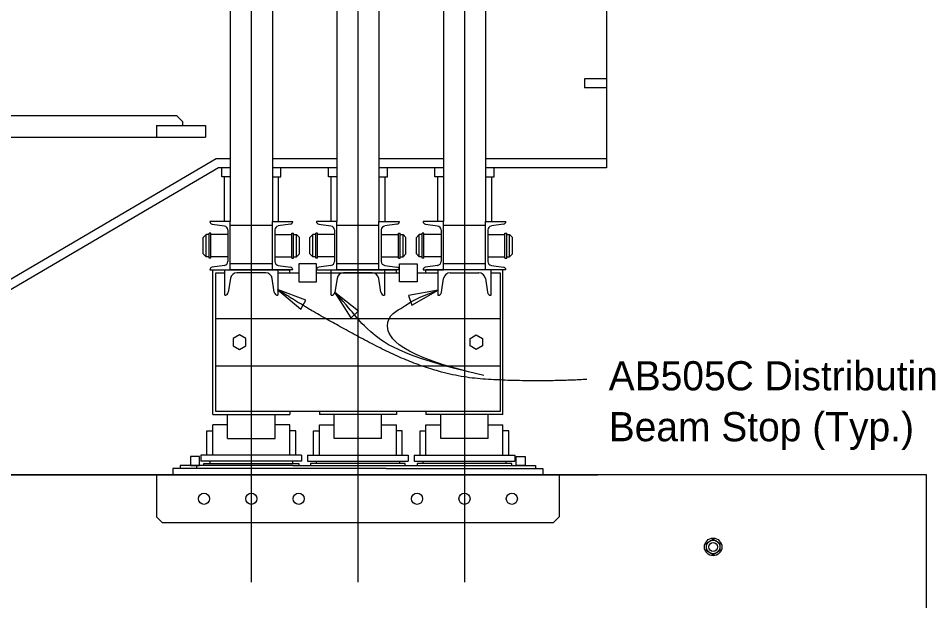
# Model space of a CAD drawing. Extents: x -4.4 to 30.2, y 1.2 to 17.8.
# Drawn here: x 22.971 to 27.789, y 8.08 to 11.153 of the extents above; entities that cross this region are included whole.
import ezdxf

# ---------------------------------------------------------------- set-up
doc = ezdxf.new("R2010")
doc.units = 0
for name, color, linetype in [('CL_Minor', 7, 'Continuous'), ('Dimension', 7, 'Continuous'), ('Miscellaneous', 7, 'Continuous'), ('SteelMisc', 7, 'Continuous'), ('Wood', 7, 'Continuous')]:
    doc.layers.add(name, color=color, linetype=linetype)

msp = doc.modelspace()

# ---------------------------------------------------------------- linework, layer by layer
at = {"layer": 'CL_Minor'}
for p, q in [((25.3273, 17.6955), (25.3273, 8.1779)), ((24.2019, 16.9098), (24.2019, 8.1779)), ((24.7646, 16.9098), (24.7646, 8.1779))]:
    msp.add_line(p, q, dxfattribs=at)
at = {"layer": 'Dimension'}
for points in [[(24.3408, 9.7224), (24.4626, 9.6193), (24.4892, 9.6658)], [(24.7293, 9.573), (24.643, 9.7082), (24.7683, 9.6095)], [(25.188, 9.7195), (25.0321, 9.6905), (25.0502, 9.6399)]]:
    msp.add_lwpolyline(points, close=True, dxfattribs=at)
for points, degree in [([(25.974, 9.2475), (25.6657, 9.2315), (25.152, 9.2707), (24.5315, 9.5973), (24.3408, 9.7224)], 2), ([(25.429, 9.2693), (24.98, 9.3691), (24.7927, 9.5306), (24.7496, 9.5842), (24.7132, 9.6307), (24.643, 9.7082)], 3), ([(25.429, 9.2693), (24.98, 9.3691), (24.8654, 9.5681), (25.0288, 9.6326), (25.0332, 9.6602), (25.188, 9.7195)], 3)]:
    msp.add_open_spline(points, degree=degree, dxfattribs=at)
at = {"layer": 'Miscellaneous'}
for points in [[(23.9831, 8.8167), (23.9831, 8.8048), (24.4208, 8.8048), (24.4208, 8.8167)], [(24.9834, 8.8167), (24.9834, 8.8048), (24.5457, 8.8048), (24.5457, 8.8167)], [(25.5461, 8.8167), (25.5461, 8.8048), (25.1084, 8.8048), (25.1084, 8.8167)], [(23.9517, 8.8048), (24.4521, 8.8048), (24.4521, 8.7929)], [(23.9517, 8.7929), (23.9517, 8.8048)], [(25.0148, 8.8048), (24.5144, 8.8048), (24.5144, 8.7929)], [(25.0148, 8.7929), (25.0148, 8.8048)], [(25.5775, 8.8048), (25.0771, 8.8048), (25.0771, 8.7929)], [(25.5775, 8.7929), (25.5775, 8.8048)]]:
    msp.add_lwpolyline(points, dxfattribs=at)
at = {"layer": 'SteelMisc'}
for p, q in [((24.0906, 13.4491), (24.0906, 10.0806)), ((25.2161, 13.4491), (25.2161, 10.0806)), ((25.4385, 13.4491), (25.4385, 10.0806)), ((24.3131, 13.3329), (24.3131, 10.0806)), ((24.6534, 12.6443), (24.6534, 10.0806)), ((24.8758, 12.3396), (24.8758, 10.0806)), ((26.0776, 11.2551), (26.0776, 10.3648)), ((26.0776, 10.8338), (25.9607, 10.8338)), ((25.9607, 10.8338), (25.9607, 10.7861)), ((26.0776, 10.7861), (25.9607, 10.7861)), ((19.4067, 10.6401), (23.8077, 10.6401)), ((23.8077, 10.6401), (23.839, 10.6081)), ((23.839, 10.6081), (23.839, 10.5874)), ((23.7007, 10.5874), (23.9602, 10.5874)), ((23.7007, 10.5874), (23.7007, 10.5256)), ((23.9602, 10.5874), (23.9602, 10.5256)), ((19.1446, 10.5256), (23.9602, 10.5256)), ((24.0156, 10.4125), (22.5807, 9.5699)), ((24.0906, 10.4125), (24.0156, 10.4125)), ((24.6534, 10.4125), (24.3131, 10.4125)), ((25.2161, 10.4125), (24.8758, 10.4125)), ((26.0776, 10.4125), (25.4385, 10.4125)), ((24.0281, 10.3648), (22.5933, 9.5222)), ((24.0906, 10.3648), (24.0281, 10.3648)), ((24.0459, 10.3171), (24.0459, 10.3648)), ((24.6534, 10.3648), (24.3131, 10.3648)), ((24.3578, 10.3171), (24.3578, 10.3648)), ((24.6086, 10.3171), (24.6086, 10.3648)), ((25.2161, 10.3648), (24.8758, 10.3648)), ((24.9205, 10.3171), (24.9205, 10.3648)), ((25.1713, 10.3171), (25.1713, 10.3648)), ((26.0776, 10.3648), (25.4385, 10.3648)), ((25.4832, 10.3171), (25.4832, 10.3648)), ((24.0906, 10.3171), (24.0459, 10.3171)), ((24.0593, 10.3171), (24.0593, 10.0806)), ((24.3131, 10.3171), (24.3578, 10.3171)), ((24.3444, 10.3171), (24.3444, 10.0806)), ((24.6534, 10.3171), (24.6086, 10.3171)), ((24.6221, 10.3171), (24.6221, 10.0806)), ((24.8758, 10.3171), (24.9205, 10.3171)), ((24.9071, 10.3171), (24.9071, 10.0806)), ((25.2161, 10.3171), (25.1713, 10.3171)), ((25.1848, 10.3171), (25.1848, 10.0806)), ((25.4385, 10.3171), (25.4832, 10.3171)), ((25.4698, 10.3171), (25.4698, 10.0806)), ((24.0906, 10.0806), (23.983, 10.0806)), ((24.0906, 9.8263), (24.0906, 10.0806)), ((24.3131, 10.0806), (24.4207, 10.0806)), ((24.3131, 9.8263), (24.3131, 10.0806)), ((24.6534, 10.0806), (24.5457, 10.0806)), ((24.6534, 9.8263), (24.6534, 10.0806)), ((24.8758, 10.0806), (24.9834, 10.0806)), ((24.8758, 9.8263), (24.8758, 10.0806)), ((25.2161, 10.0806), (25.1085, 10.0806)), ((25.2161, 9.8263), (25.2161, 10.0806)), ((25.4385, 10.0806), (25.5461, 10.0806)), ((25.4385, 9.8263), (25.4385, 10.0806)), ((23.9954, 10.0669), (24.0597, 10.0573)), ((24.0781, 10.0369), (24.0781, 9.87)), ((24.0906, 10.0623), (24.3131, 10.0623)), ((24.3256, 10.0369), (24.3256, 9.87)), ((24.4083, 10.0669), (24.344, 10.0573)), ((24.5582, 10.0669), (24.6225, 10.0573)), ((24.6409, 10.0369), (24.6409, 9.87)), ((24.6534, 10.0623), (24.8758, 10.0623)), ((24.8883, 10.0369), (24.8883, 9.87)), ((24.971, 10.0669), (24.9067, 10.0573)), ((25.1209, 10.0669), (25.1852, 10.0573)), ((25.2036, 10.0369), (25.2036, 9.87)), ((25.2161, 10.0623), (25.4385, 10.0623)), ((25.451, 10.0369), (25.451, 9.87)), ((25.5337, 10.0669), (25.4694, 10.0573)), ((23.9635, 10.0122), (23.9479, 9.9963)), ((23.9479, 9.9106), (23.9479, 9.9963)), ((23.9635, 9.8947), (23.9635, 10.0122)), ((23.9791, 10.0122), (23.9635, 10.0122)), ((23.9791, 9.8871), (23.9791, 10.0198)), ((23.9879, 10.0198), (23.9791, 10.0198)), ((23.9879, 9.8871), (23.9879, 10.0198)), ((24.0781, 10.0122), (23.9879, 10.0122)), ((24.3256, 10.0122), (24.4158, 10.0122)), ((24.4158, 10.0198), (24.4246, 10.0198)), ((24.4158, 9.8871), (24.4158, 10.0198)), ((24.4246, 9.8871), (24.4246, 10.0198)), ((24.4246, 10.0122), (24.4402, 10.0122)), ((24.4402, 9.8947), (24.4402, 10.0122)), ((24.4402, 10.0122), (24.4558, 9.9963)), ((24.4558, 9.9106), (24.4558, 9.9963)), ((24.5262, 10.0122), (24.5106, 9.9963)), ((24.5106, 9.9106), (24.5106, 9.9963)), ((24.5262, 9.8947), (24.5262, 10.0122)), ((24.5418, 10.0122), (24.5262, 10.0122)), ((24.5418, 9.8871), (24.5418, 10.0198)), ((24.5506, 10.0198), (24.5418, 10.0198)), ((24.5506, 9.8871), (24.5506, 10.0198)), ((24.6409, 10.0122), (24.5506, 10.0122)), ((24.8883, 10.0122), (24.9785, 10.0122)), ((24.9785, 10.0198), (24.9873, 10.0198)), ((24.9785, 9.8871), (24.9785, 10.0198)), ((24.9873, 9.8871), (24.9873, 10.0198)), ((24.9873, 10.0122), (25.0029, 10.0122)), ((25.0029, 9.8947), (25.0029, 10.0122)), ((25.0029, 10.0122), (25.0185, 9.9963)), ((25.0185, 9.9106), (25.0185, 9.9963)), ((25.0889, 10.0122), (25.0733, 9.9963)), ((25.0733, 9.9106), (25.0733, 9.9963)), ((25.0889, 9.8947), (25.0889, 10.0122)), ((25.1045, 10.0122), (25.0889, 10.0122)), ((25.1045, 9.8871), (25.1045, 10.0198)), ((25.1133, 10.0198), (25.1045, 10.0198)), ((25.1133, 9.8871), (25.1133, 10.0198)), ((25.2036, 10.0122), (25.1133, 10.0122)), ((25.451, 10.0122), (25.5412, 10.0122)), ((25.5412, 10.0198), (25.5501, 10.0198)), ((25.5412, 9.8871), (25.5412, 10.0198)), ((25.5501, 9.8871), (25.5501, 10.0198)), ((25.5501, 10.0122), (25.5657, 10.0122)), ((25.5657, 9.8947), (25.5657, 10.0122)), ((25.5657, 10.0122), (25.5813, 9.9963)), ((25.5813, 9.9106), (25.5813, 9.9963)), ((23.9635, 9.8947), (23.9479, 9.9106)), ((23.9791, 9.8947), (23.9635, 9.8947)), ((23.9879, 9.8871), (23.9791, 9.8871)), ((24.0781, 9.8947), (23.9879, 9.8947)), ((24.3256, 9.8947), (24.4158, 9.8947)), ((24.4158, 9.8871), (24.4246, 9.8871)), ((24.4246, 9.8947), (24.4402, 9.8947)), ((24.4402, 9.8947), (24.4558, 9.9106)), ((24.5262, 9.8947), (24.5106, 9.9106)), ((24.5418, 9.8947), (24.5262, 9.8947)), ((24.5506, 9.8871), (24.5418, 9.8871)), ((24.6409, 9.8947), (24.5506, 9.8947)), ((24.8883, 9.8947), (24.9785, 9.8947)), ((24.9785, 9.8871), (24.9873, 9.8871)), ((24.9873, 9.8947), (25.0029, 9.8947)), ((25.0029, 9.8947), (25.0185, 9.9106)), ((25.0889, 9.8947), (25.0733, 9.9106)), ((25.1045, 9.8947), (25.0889, 9.8947)), ((25.1133, 9.8871), (25.1045, 9.8871)), ((25.2036, 9.8947), (25.1133, 9.8947)), ((25.451, 9.8947), (25.5412, 9.8947)), ((25.5412, 9.8871), (25.5501, 9.8871)), ((25.5501, 9.8947), (25.5657, 9.8947)), ((25.5657, 9.8947), (25.5813, 9.9106)), ((24.0597, 9.8496), (23.9954, 9.84)), ((24.3131, 9.8581), (24.0906, 9.8581)), ((24.344, 9.8496), (24.4083, 9.84)), ((24.6225, 9.8496), (24.5582, 9.84)), ((24.8758, 9.8581), (24.6534, 9.8581)), ((24.9067, 9.8496), (24.971, 9.84)), ((25.1852, 9.8496), (25.1209, 9.84)), ((25.4385, 9.8581), (25.2161, 9.8581)), ((25.4694, 9.8496), (25.5337, 9.84)), ((23.983, 9.8263), (24.0906, 9.8263)), ((23.9987, 9.0631), (23.9987, 9.8263)), ((23.9987, 9.8263), (24.4051, 9.8263)), ((24.0612, 9.6918), (24.0612, 9.8263)), ((24.0612, 9.8263), (24.3425, 9.8263)), ((24.0917, 9.7808), (24.0803, 9.7082)), ((24.3131, 9.8263), (24.0906, 9.8263)), ((24.2781, 9.81), (24.1257, 9.81)), ((24.3234, 9.7082), (24.312, 9.7808)), ((24.4207, 9.8263), (24.3131, 9.8263)), ((24.3425, 9.8263), (24.3425, 9.6918)), ((24.4051, 9.8104), (24.4051, 9.8263)), ((24.5457, 9.8263), (24.6534, 9.8263)), ((24.5614, 9.8263), (24.9679, 9.8263)), ((24.6239, 9.6918), (24.6239, 9.8263)), ((24.6239, 9.8263), (24.9053, 9.8263)), ((24.6544, 9.7808), (24.643, 9.7082)), ((24.8758, 9.8263), (24.6534, 9.8263)), ((24.8408, 9.81), (24.6884, 9.81)), ((24.8861, 9.7082), (24.8747, 9.7808)), ((24.9834, 9.8263), (24.8758, 9.8263)), ((24.9053, 9.8263), (24.9053, 9.6918)), ((24.9679, 9.8104), (24.9679, 9.8263)), ((25.1085, 9.8263), (25.2161, 9.8263)), ((25.1241, 9.8104), (25.1241, 9.8263)), ((25.5305, 9.8263), (25.1241, 9.8263)), ((25.1868, 9.8263), (25.1868, 9.6918)), ((25.4682, 9.8263), (25.1868, 9.8263)), ((25.206, 9.7082), (25.2173, 9.7808)), ((25.4385, 9.8263), (25.2161, 9.8263)), ((25.2513, 9.81), (25.4037, 9.81)), ((25.4377, 9.7808), (25.449, 9.7082)), ((25.5461, 9.8263), (25.4385, 9.8263)), ((25.4682, 9.6918), (25.4682, 9.8263)), ((25.5305, 9.0631), (25.5305, 9.8263)), ((24.0143, 9.5694), (25.5149, 9.5694)), ((24.0143, 9.32), (25.5149, 9.32)), ((23.9987, 9.0631), (24.4051, 9.0631)), ((24.0768, 8.9359), (24.0768, 9.0631)), ((24.327, 8.9359), (24.327, 9.0631)), ((24.4051, 9.079), (24.4051, 9.0631)), ((24.5614, 9.079), (24.5614, 9.0631)), ((24.9678, 9.0631), (24.5614, 9.0631)), ((24.6395, 8.9359), (24.6395, 9.0631)), ((24.8897, 8.9359), (24.8897, 9.0631)), ((24.9678, 9.079), (24.9678, 9.0631)), ((25.1241, 9.079), (25.1241, 9.0631)), ((25.5305, 9.0631), (25.1241, 9.0631)), ((25.2022, 8.9359), (25.2022, 9.0631)), ((25.4524, 8.9359), (25.4524, 9.0631)), ((23.9674, 8.8485), (23.9674, 8.9757)), ((23.9674, 8.9757), (23.9987, 8.9757)), ((23.9987, 8.8485), (23.9987, 9.0075)), ((24.0768, 9.0075), (23.9987, 9.0075)), ((24.4051, 9.0075), (24.327, 9.0075)), ((24.4051, 8.8485), (24.4051, 9.0075)), ((24.4364, 8.9757), (24.4051, 8.9757)), ((24.4364, 8.8485), (24.4364, 8.9757)), ((24.5301, 8.8485), (24.5301, 8.9757)), ((24.5301, 8.9757), (24.5614, 8.9757)), ((24.5614, 8.8485), (24.5614, 9.0075)), ((24.5614, 9.0075), (24.6395, 9.0075)), ((24.8897, 9.0075), (24.9678, 9.0075)), ((24.9678, 8.8485), (24.9678, 9.0075)), ((24.9991, 8.9757), (24.9678, 8.9757)), ((24.9991, 8.8485), (24.9991, 8.9757)), ((25.0928, 8.8485), (25.0928, 8.9757)), ((25.0928, 8.9757), (25.1241, 8.9757)), ((25.1241, 8.8485), (25.1241, 9.0075)), ((25.1241, 9.0075), (25.2022, 9.0075)), ((25.4524, 9.0075), (25.5305, 9.0075)), ((25.5305, 8.8485), (25.5305, 9.0075)), ((25.5618, 8.9757), (25.5305, 8.9757)), ((25.5618, 8.8485), (25.5618, 8.9757)), ((24.0768, 8.9359), (24.327, 8.9359)), ((24.8897, 8.9359), (24.6395, 8.9359)), ((25.4524, 8.9359), (25.2022, 8.9359)), ((24.4677, 8.8485), (23.9361, 8.8485)), ((23.9361, 8.8485), (23.9361, 8.8167)), ((24.4676, 8.8167), (23.9361, 8.8167)), ((24.4677, 8.8485), (24.4677, 8.8167)), ((24.4989, 8.8485), (24.4988, 8.8167)), ((24.4989, 8.8485), (25.0304, 8.8485)), ((24.4989, 8.8167), (25.0304, 8.8167)), ((25.0304, 8.8485), (25.0304, 8.8167)), ((25.0616, 8.8485), (25.0615, 8.8167)), ((25.0616, 8.8485), (25.5931, 8.8485)), ((25.0616, 8.8167), (25.5931, 8.8167)), ((25.5931, 8.8485), (25.5931, 8.8167)), ((23.7877, 8.777), (23.7877, 8.7452)), ((24.9132, 8.777), (23.7877, 8.777)), ((23.9132, 8.7929), (23.9132, 8.777)), ((24.9132, 8.777), (25.7415, 8.777)), ((25.7415, 8.777), (25.7415, 8.7452)), ((3.2586, 8.7452), (26.0322, 8.7452)), ((23.7016, 8.7452), (23.7016, 8.5227)), ((25.8275, 8.7452), (25.8275, 8.5227)), ((23.7329, 8.4909), (23.7016, 8.5227)), ((25.7962, 8.4909), (23.7329, 8.4909)), ((25.8275, 8.5227), (25.7962, 8.4909))]:
    msp.add_line(p, q, dxfattribs=at)
for points in [[(24.452, 9.7627), (24.5458, 9.7627), (24.5458, 9.8581), (24.452, 9.8581)], [(25.0773, 9.7627), (24.9835, 9.7627), (24.9835, 9.8581), (25.0773, 9.8581)], [(24.1726, 9.4252), (24.1726, 9.4642), (24.1394, 9.4837), (24.1061, 9.4642), (24.1061, 9.4252), (24.1394, 9.4057)], [(25.3566, 9.4252), (25.3566, 9.4642), (25.3898, 9.4837), (25.4231, 9.4642), (25.4231, 9.4252), (25.3898, 9.4057)], [(23.8814, 8.7929), (23.9283, 8.7929), (23.9283, 8.8406), (23.8814, 8.8406)], [(25.6478, 8.7929), (25.6009, 8.7929), (25.6009, 8.8406), (25.6478, 8.8406)], [(26.6759, 8.3845), (26.6759, 8.3428), (26.6403, 8.3219), (26.6048, 8.3428), (26.6048, 8.3845), (26.6403, 8.4054)]]:
    msp.add_lwpolyline(points, close=True, dxfattribs=at)
for points in [[(25.4682, 9.8104), (25.5149, 9.8104), (25.5149, 9.079), (24.0143, 9.079), (24.0143, 9.8104), (24.0612, 9.8104)], [(24.3425, 9.8104), (24.452, 9.8104)], [(24.5458, 9.8104), (24.9835, 9.8104)], [(25.0773, 9.8104), (25.1868, 9.8104)], [(24.4217, 8.7929), (23.8267, 8.7929), (23.8267, 8.777)], [(24.4217, 8.7929), (25.7025, 8.7929), (25.7025, 8.777)]]:
    msp.add_lwpolyline(points, dxfattribs=at)
for centre, major_axis, ratio, start_param, end_param in [((23.9979, 10.0806), (-0.0149, 0), 0.936129, 6.283185, 7.688175), ((24.4058, 10.0806), (0.0149, 0), 0.936129, 4.878195, 6.283185), ((24.5606, 10.0806), (-0.0149, 0), 0.936129, 6.283185, 7.688175), ((24.9685, 10.0806), (0.0149, 0), 0.936129, 4.878195, 6.283185), ((25.1233, 10.0806), (-0.0149, 0), 0.936129, 6.283185, 7.688175), ((25.5313, 10.0806), (0.0149, 0), 0.936129, 4.878195, 6.283185), ((24.0561, 10.0369), (0.022, 0), 0.936129, 6.283185, 7.688175), ((24.3476, 10.0369), (-0.022, 0), 0.936129, 4.878195, 6.283185), ((24.6188, 10.0369), (0.022, 0), 0.936129, 6.283185, 7.688175), ((24.9103, 10.0369), (-0.022, 0), 0.936129, 4.878195, 6.283185), ((25.1815, 10.0369), (0.022, 0), 0.936129, 6.283185, 7.688175), ((25.473, 10.0369), (-0.022, 0), 0.936129, 4.878195, 6.283185), ((23.9979, 9.8263), (-0.0149, 0), 0.936129, 4.878195, 6.283185), ((24.0561, 9.87), (0.022, 0), 0.936129, 4.878195, 6.283185), ((24.3476, 9.87), (-0.022, 0), 0.936129, 0, 1.40499), ((24.4058, 9.8263), (0.0149, 0), 0.936129, 0, 1.40499), ((24.5606, 9.8263), (-0.0149, 0), 0.936129, 4.878195, 6.283185), ((24.6188, 9.87), (0.022, 0), 0.936129, 4.878195, 6.283185), ((24.9103, 9.87), (-0.022, 0), 0.936129, 0, 1.40499), ((24.9685, 9.8263), (0.0149, 0), 0.936129, 0, 1.40499), ((25.1233, 9.8263), (-0.0149, 0), 0.936129, 4.878195, 6.283185), ((25.1815, 9.87), (0.022, 0), 0.936129, 4.878195, 6.283185), ((25.473, 9.87), (-0.022, 0), 0.936129, 0, 1.40499), ((25.5313, 9.8263), (0.0149, 0), 0.936129, 0, 1.40499), ((24.1257, 9.775), (0, 0.035), 0.983193, 0, 1.40499), ((24.2781, 9.775), (0, 0.035), 0.983193, 4.878195, 6.283185), ((24.6884, 9.775), (0, 0.035), 0.983193, 0, 1.40499), ((24.8408, 9.775), (0, 0.035), 0.983193, 4.878195, 6.283185), ((25.2513, 9.775), (0, -0.035), 0.983193, 3.141593, 4.546583), ((25.4037, 9.775), (0, 0.035), 0.983193, 4.878195, 6.283185), ((24.0612, 9.7115), (0, 0.0197), 0.983193, 3.141593, 4.546583), ((24.3425, 9.7115), (0, -0.0197), 0.983193, 4.878195, 6.283185), ((24.6239, 9.7115), (0, 0.0197), 0.983193, 3.141593, 4.546583), ((24.9053, 9.7115), (0, -0.0197), 0.983193, 4.878195, 6.283185), ((25.1868, 9.7115), (0, -0.0197), 0.983193, 6.283185, 7.688175), ((25.4682, 9.7115), (0, -0.0197), 0.983193, 4.878195, 6.283185)]:
    msp.add_ellipse(centre, major_axis=major_axis, ratio=ratio, start_param=start_param, end_param=end_param, dxfattribs=at)
for centre, major_axis in [((23.9517, 8.618), (0, 0.0298)), ((24.2019, 8.618), (0, 0.0298)), ((24.4519, 8.618), (0, 0.0298)), ((25.0772, 8.618), (0, -0.0298)), ((25.3273, 8.618), (0, -0.0298)), ((25.5774, 8.618), (0, -0.0298)), ((26.6403, 8.3637), (0, 0.0467)), ((26.6403, 8.3637), (0, 0.0362)), ((26.6403, 8.3637), (0, 0.0238))]:
    msp.add_ellipse(centre, major_axis=major_axis, ratio=0.983193, dxfattribs=at)
at = {"layer": 'Wood'}
for p, q in [((27.7658, 8.7452), (14.6356, 8.7452)), ((27.7658, 7.9821), (27.7658, 8.7452))]:
    msp.add_line(p, q, dxfattribs=at)

# ---------------------------------------------------------------- texts
at = {"layer": 'Dimension'}
for s, p in [('AB505C Distributing ', (26.0886, 9.1902)), ('Beam Stop (Typ.)', (26.0886, 8.9215))]:
    msp.add_text(s, height=0.153845, dxfattribs=at).set_placement(p)

doc.saveas('drawing.dxf')
